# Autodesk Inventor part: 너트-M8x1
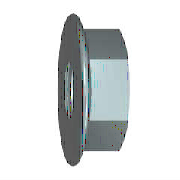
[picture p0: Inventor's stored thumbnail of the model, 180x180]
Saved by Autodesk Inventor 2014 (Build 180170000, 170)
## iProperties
Created: 2015-12
Part Number: 너트-M8x1
Material: 스테인리스강
Description: 플랜지붙이 6각 너트 - 일반 스레드
Document SubType Name: Modeling
Standard: ISO 4161
Designer: mdu
Standard Revision: 2판 1999-03-15
Standards Organization: ISO
Language: ko-KR
Size Designation: M8
Categories: <MemberInstance><Categories><Category DisplayName="조임쇠" InternalName="e4da775c-781d-43d5-af7c-5136215cf5a6" Mnemonic="FSTN"><Category DisplayName="너트" InternalN
Density: 8.08 g/cm^3
Appearance: 노란색
Mass: 9.03298 g
Surface Area: 8.90186 cm^2
Volume: 1.11794 cm^3
Author: mdu
IsCustomPart: 1
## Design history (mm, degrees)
sketch "스케치1"
  geometry: L1 (-1.844, 0)-(9.641, 0) reference; L2 (3.107, 6.5)-(2.288, 8.257); L3 (3.107, 6.5)-(8, 6.5); L4 (8, 6.5)-(8, 0); L5 (3.107, 6.5)-(3.107, 0); L6 (0, -1.835)-(0, 11.01) reference; A1 r 1.2 centre (1.2, 7.75) between (2.288, 8.257) and (0, 7.75); 1 further point
  constraints: 8 end point, 3 point on line, 2 perpendicular, 2 point on circle, 2 tangent, 1 centre point, 1 parallel
  dimensions: "d2" = 13 diameter of L3 L1 (= SW); "d4" = 17.9 dimension on A1 L1 (= LADI); "d5" = 1.2 radius of A1 (= PHH); "d15" = 8 distance between parallel lines of L4 L6 (= KOH); "d16" = 25 deg angle of L6 L2 (= KEWI)
revolve "링" sketch "스케치1" stored, may be unused: angle "d8" = 90 deg
sketch "스케치2"
  geometry: L1 (-6.5, -3.753)-(-6.5, 3.753); L2 (-6.5, 3.753)-(0, 7.506); L3 (0, 7.506)-(6.5, 3.753); L4 (6.5, 3.753)-(6.5, -3.753); L5 (6.5, -3.753)-(0, -7.506); L6 (0, -7.506)-(-6.5, -3.753); C1 r 4.9 at (0, 0); C2 r 7.75 at (0, 0) reference; 1 further point
  constraints: 12 end point, 1 centre point, 1 coincident, 1 vertical, 11 other
  dimensions: "d6" = 15.01111 distance of L5.end L2.end (= 1.1547 x SW)
extrude "본체" join sketch "스케치2" distance "d7" = 8 (= KOH); taper "d9" = 0 deg
sketch "스케치3"
  geometry: L1 (2.638, 7.506)-(8, 7.506) reference; L2 (8, 3.753)-(8, 7.506) reference; L3 (0, -7.75)-(0, 7.75) reference; L4 (-1.6, 0)-(9.6, 0) reference; L5 (7.419, 7.506)-(8, 6.5)
  constraints: 2 end point, 2 point on line
  dimensions: "d10" = 30 deg angle of L2 L5 (= ANG1); "d11" = 13 diameter of L5.end L4 (= SW0)
revolve "모따기1" sketch "스케치3" stored, may be unused: angle "d24" = 90 deg
sketch "스케치4"
  geometry: C1 r 7.75 at (0, 0) reference; 1 further point
  constraints: 1 coincident
hole "스레드" sketch "스케치4" at (0, 0) diameter "d25" = 6.647; stored, may be unused: countersink angle "d29" = 82 deg, drill point angle "d31" = 118 deg; dims "d26" = 6, "d27" = 4, "d28" = 2, "d30" = 8
workaxis "Work Axis1"
workplane "Work Plane1"
body "Solid1"
chamfer "모따기2" distance "d12" = 0.67658 (= -0.5 x GD1 + 0.5 x NND); stored, may be unused: angle "d13" = 30 deg, second distance "d46" = 0.67658 (= -0.5 x GD1 + 0.5 x NND)
chamfer "모따기3" distance "d51" = 0.67658 (= -0.5 x GD1 + 0.5 x NND); stored, may be unused: second distance "d52" = 2, angle "d53" = 45 deg
other parameters: "ANG1" = 30 deg [user parameter; used in 1 equation term], "KEWI" = 25 deg [user parameter; used in 1 equation term], "NND" = 8 [user parameter; used in 4 equation terms], "LADI" = 17.9 [user parameter; used in 2 equation terms], "SW" = 13 [user parameter; used in 3 equation terms], "PHH" = 1.2 [user parameter; used in 3 equation terms], "KOH" = 8 (= NND) [user parameter; used in 2 equation terms], "SW0" = 13 [user parameter; used in 1 equation term], "GD1" = 6.64684 (computed from THREADDIA, PTC, TOA) [user parameter; used in 3 equation terms], "d1" = 17.9 (= LADI), "d3" = 1.2 (= PHH), "d45" = 0, "d47" = 0, "d49" = 0, "d54" = 0, "GUL" = 0.67658 (= 0.541266 x PTC) [user parameter], "TPU" = 8 (computed from PTC) [user parameter], "RR" = 1.2 (= PHH) [user parameter], "THREADDIA" = 8 [user parameter; used in 1 equation term], "TOA" = 30 deg [user parameter; used in 1 equation term], "PTC" = 1.25 [user parameter; used in 4 equation terms], "GAL" = 0.67658 (= 0.541266 x PTC) [user parameter], "E0" = 15.015 (= 1.155 x SW) [user parameter]
